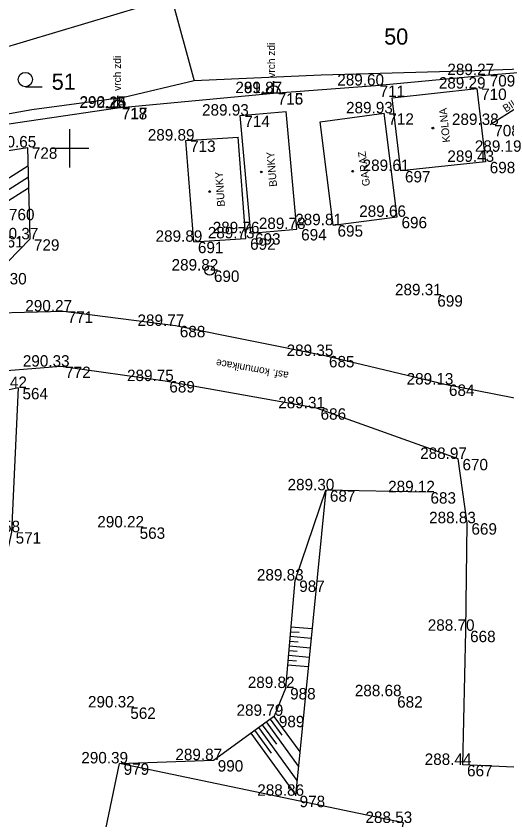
# Model space of a CAD drawing. Extents: x -599970 to -599524, y -1154772 to -1154457.
# Drawn here: x -599702.82 to -599677.05, y -1154635.29 to -1154593.05 of the extents above; entities that cross this region are included whole.
import ezdxf

# ---------------------------------------------------------------- set-up
doc = ezdxf.new("R2010")
doc.units = 0
for name, color, linetype in [('Z-BUDOVY', 7, 'Continuous'), ('Z-KANALIZACNI SACHTY VPUSTI', 7, 'Continuous'), ('Z-KATASTRALNI MAPA', 7, 'Continuous'), ('Z-KRIZKY CTVERCOVE SITE', 7, 'Continuous'), ('Z-PLOT BETONOVY', 7, 'Continuous'), ('Z-PLOT DRATENY', 7, 'Continuous'), ('Z-PODROBNE BODY', 7, 'Continuous'), ('Z-PODROBNE BODY-CISLO', 7, 'Continuous'), ('Z-PODROBNE BODY-VYSKA', 7, 'Continuous'), ('Z-POPISY OBJEKTU A ZPEVNENYCH PLOCH', 7, 'Continuous'), ('Z-SCHODY', 7, 'Continuous'), ('Z-SRAFOVANI SVAHU', 7, 'Continuous'), ('Z-TERENNI HRANY PATY', 7, 'Continuous'), ('Z-VYSKOVE BODY', 7, 'Continuous'), ('Z-ZPEVNENE PLOCHY', 7, 'Continuous')]:
    doc.layers.add(name, color=color, linetype=linetype)

msp = doc.modelspace()

# ---------------------------------------------------------------- linework, layer by layer
at = {"layer": 'Z-BUDOVY'}
for p, q in [((-599688.08, -1154604.24), (-599688.64, -1154598.06)), ((-599682.81, -1154603.6), (-599683.5, -1154598.16)), ((-599690.76, -1154604.73), (-599691.17, -1154599.41))]:
    msp.add_line(p, q, dxfattribs=at)
for points in [[(-599682.63, -1154601.19), (-599683.08, -1154597.34), (-599678.63, -1154596.86), (-599678.18, -1154600.71), (-599682.63, -1154601.19)], [(-599690.5, -1154604.46), (-599691.06, -1154598.28), (-599688.64, -1154598.06)], [(-599686.17, -1154604.04), (-599686.86, -1154598.6), (-599683.5, -1154598.16)], [(-599693.5, -1154604.91), (-599693.91, -1154599.59), (-599691.17, -1154599.41)], [(-599686.17, -1154604.04), (-599682.81, -1154603.6)], [(-599690.5, -1154604.46), (-599688.08, -1154604.24)], [(-599693.5, -1154604.91), (-599690.76, -1154604.73)], [(-599684.7, -1154645.47), (-599699.48, -1154642.29), (-599697.4, -1154632.32)], [(-599684.7, -1154645.47), (-599682.48, -1154635.45), (-599697.4, -1154632.32)]]:
    msp.add_lwpolyline(points, dxfattribs=at)
at = {"layer": 'Z-KANALIZACNI SACHTY VPUSTI'}
msp.add_circle((-599692.66, -1154606.42), 0.25, dxfattribs=at)
at = {"layer": 'Z-KATASTRALNI MAPA'}
for p, q in [((-599694.67, -1154592.08), (-599720.86, -1154599.93)), ((-599694.67, -1154592.08), (-599693.47, -1154596.46)), ((-599702.336, -1154596.76), (-599701.461, -1154596.76))]:
    msp.add_line(p, q, dxfattribs=at)
for points in [[(-599673.37, -1154595.74), (-599678.74, -1154595.92), (-599686.81, -1154596.16), (-599693.47, -1154596.46)], [(-599693.47, -1154596.46), (-599697.17, -1154597.32), (-599702, -1154597.98), (-599710.88, -1154599.57), (-599714.17, -1154599.94), (-599720.86, -1154599.93)]]:
    msp.add_lwpolyline(points, dxfattribs=at)
msp.add_circle((-599702.336, -1154596.385), 0.375, dxfattribs=at)
at = {"layer": 'Z-KRIZKY CTVERCOVE SITE'}
for p, q in [((-599700, -1154601), (-599700, -1154599)), ((-599699, -1154600), (-599701, -1154600))]:
    msp.add_line(p, q, dxfattribs=at)
at = {"layer": 'Z-PLOT BETONOVY'}
msp.add_lwpolyline([(-599697.5, -1154597.88), (-599689.31, -1154597.1), (-599683.96, -1154596.7), (-599678.18, -1154596.15), (-599673.7, -1154595.78)], dxfattribs=at)
at = {"layer": 'Z-PLOT DRATENY'}
for points in [[(-599741.2, -1154597.57), (-599735.3, -1154599.31), (-599728.67, -1154601.06), (-599725.81, -1154601.09), (-599719.24, -1154600.72), (-599713.57, -1154600.28), (-599704.41, -1154598.89), (-599697.5, -1154597.88)], [(-599681.29, -1154618.07), (-599686.57, -1154617.97), (-599688.16, -1154634.02)]]:
    msp.add_lwpolyline(points, dxfattribs=at)
at = {"layer": 'Z-PODROBNE BODY'}
for p, q in [((-599678.18, -1154596.15), (-599678.18, -1154596.15)), ((-599689.31, -1154597.1), (-599689.31, -1154597.1)), ((-599689.31, -1154597.1), (-599689.31, -1154597.1)), ((-599683.96, -1154596.7), (-599683.96, -1154596.7)), ((-599678.63, -1154596.86), (-599678.63, -1154596.86)), ((-599697.5, -1154597.88), (-599697.5, -1154597.88)), ((-599697.49, -1154597.86), (-599697.49, -1154597.86)), ((-599691.06, -1154598.28), (-599691.06, -1154598.28)), ((-599683.5, -1154598.16), (-599683.5, -1154598.16)), ((-599677.94, -1154598.77), (-599677.94, -1154598.77)), ((-599693.91, -1154599.59), (-599693.91, -1154599.59)), ((-599702.22, -1154599.95), (-599702.22, -1154599.95)), ((-599678.18, -1154600.71), (-599678.18, -1154600.71)), ((-599682.63, -1154601.19), (-599682.63, -1154601.19)), ((-599682.81, -1154603.6), (-599682.81, -1154603.6)), ((-599688.08, -1154604.24), (-599688.08, -1154604.24)), ((-599686.17, -1154604.04), (-599686.17, -1154604.04)), ((-599690.5, -1154604.46), (-599690.5, -1154604.46)), ((-599702.11, -1154604.78), (-599702.11, -1154604.78)), ((-599693.5, -1154604.91), (-599693.5, -1154604.91)), ((-599690.76, -1154604.73), (-599690.76, -1154604.73)), ((-599692.66, -1154606.42), (-599692.66, -1154606.42)), ((-599680.93, -1154607.72), (-599680.93, -1154607.72)), ((-599700.34, -1154608.57), (-599700.34, -1154608.57)), ((-599694.45, -1154609.33), (-599694.45, -1154609.33)), ((-599686.62, -1154610.91), (-599686.62, -1154610.91)), ((-599700.47, -1154611.47), (-599700.47, -1154611.47)), ((-599695, -1154612.23), (-599695, -1154612.23)), ((-599702.71, -1154612.59), (-599702.71, -1154612.59)), ((-599680.32, -1154612.41), (-599680.32, -1154612.41)), ((-599687.06, -1154613.66), (-599687.06, -1154613.66)), ((-599679.61, -1154616.32), (-599679.61, -1154616.32)), ((-599686.57, -1154617.97), (-599686.57, -1154617.97)), ((-599681.29, -1154618.07), (-599681.29, -1154618.07)), ((-599696.56, -1154619.92), (-599696.56, -1154619.92)), ((-599679.14, -1154619.7), (-599679.14, -1154619.7)), ((-599688.18, -1154622.71), (-599688.18, -1154622.71)), ((-599679.21, -1154625.35), (-599679.21, -1154625.35)), ((-599688.66, -1154628.36), (-599688.66, -1154628.36)), ((-599683.04, -1154628.79), (-599683.04, -1154628.79)), ((-599697.05, -1154629.38), (-599697.05, -1154629.38)), ((-599689.25, -1154629.82), (-599689.25, -1154629.82)), ((-599692.46, -1154632.15), (-599692.46, -1154632.15)), ((-599697.4, -1154632.32), (-599697.4, -1154632.32)), ((-599679.37, -1154632.4), (-599679.37, -1154632.4)), ((-599688.16, -1154634.02), (-599688.16, -1154634.02))]:
    msp.add_line(p, q, dxfattribs=at)
at = {"layer": 'Z-SCHODY'}
for centre in [(-599680.94, -1154598.94), (-599689.95, -1154601.24), (-599685.15, -1154601.2), (-599692.66, -1154602.27)]:
    msp.add_circle(centre, 0.0438, dxfattribs=at)
at = {"layer": 'Z-SRAFOVANI SVAHU'}
for points in [[(-599704.09, -1154602.11), (-599702.2, -1154600.92)], [(-599703.83, -1154602.54), (-599702.18, -1154601.5)], [(-599703.56, -1154602.96), (-599702.17, -1154602.08)], [(-599688.41, -1154625.4), (-599687.97, -1154625.43)], [(-599688.39, -1154625.15), (-599687.29, -1154625.24)], [(-599688.43, -1154625.64), (-599687.34, -1154625.74)], [(-599688.47, -1154626.14), (-599687.39, -1154626.24)], [(-599688.45, -1154625.89), (-599688.02, -1154625.93)], [(-599688.51, -1154626.64), (-599687.44, -1154626.73)], [(-599688.49, -1154626.39), (-599688.06, -1154626.43)], [(-599688.54, -1154626.89), (-599688.11, -1154626.93)], [(-599688.56, -1154627.14), (-599687.49, -1154627.23)], [(-599689.49, -1154630), (-599688.88, -1154630.84)], [(-599689.29, -1154629.85), (-599687.93, -1154631.72)], [(-599690.1, -1154630.44), (-599688.08, -1154633.22)], [(-599689.9, -1154630.29), (-599689.16, -1154631.31)], [(-599689.69, -1154630.14), (-599688.01, -1154632.47)], [(-599690.5, -1154630.73), (-599688.15, -1154633.97)], [(-599690.3, -1154630.58), (-599689.43, -1154631.79)]]:
    msp.add_lwpolyline(points, dxfattribs=at)
at = {"layer": 'Z-TERENNI HRANY PATY'}
for points in [[(-599729.05, -1154602.01), (-599721.76, -1154601.98), (-599713.7, -1154601.68), (-599707.23, -1154600.75), (-599702.22, -1154599.95), (-599702.11, -1154604.78), (-599703.83, -1154606.55), (-599707.44, -1154607.94), (-599715.66, -1154610.06), (-599723.72, -1154611.89), (-599730.02, -1154613.49), (-599734.59, -1154613.85), (-599735.4, -1154613.47), (-599737.38, -1154610.51), (-599738.93, -1154607.87), (-599737.97, -1154605.84), (-599735.06, -1154604.09), (-599729.05, -1154602.01)], [(-599702.71, -1154612.59), (-599705.57, -1154613.21), (-599706.65, -1154620.67), (-599709.89, -1154628.2), (-599711.28, -1154633.06)], [(-599702.71, -1154612.59), (-599703.07, -1154620.17), (-599705.22, -1154630.05), (-599705.67, -1154634.21), (-599706.5, -1154641.82), (-599707.05, -1154645.89), (-599706.85, -1154650.78)], [(-599697.4, -1154632.32), (-599692.46, -1154632.15), (-599689.25, -1154629.82), (-599688.66, -1154628.36), (-599688.18, -1154622.71), (-599686.57, -1154617.97)]]:
    msp.add_lwpolyline(points, dxfattribs=at)
at = {"layer": 'Z-VYSKOVE BODY'}
for p, q in [((-599689.31, -1154596.475), (-599689.31, -1154596.725)), ((-599689.31, -1154596.725), (-599689.31, -1154596.475)), ((-599689.31, -1154597.1), (-599689.31, -1154596.475)), ((-599689.31, -1154596.475), (-599689.31, -1154596.725)), ((-599688.685, -1154597.1), (-599689.935, -1154597.1)), ((-599689.935, -1154597.1), (-599689.31, -1154597.1)), ((-599688.685, -1154597.1), (-599689.31, -1154597.1)), ((-599697.49, -1154597.235), (-599697.49, -1154597.485)), ((-599697.49, -1154597.485), (-599697.49, -1154597.235)), ((-599697.49, -1154597.86), (-599697.49, -1154597.235)), ((-599697.49, -1154597.235), (-599697.49, -1154597.485)), ((-599696.865, -1154597.86), (-599698.115, -1154597.86)), ((-599698.115, -1154597.86), (-599697.49, -1154597.86)), ((-599696.865, -1154597.86), (-599697.49, -1154597.86))]:
    msp.add_line(p, q, dxfattribs=at)
for centre, start, end in [((-599689.31, -1154597.1), 90, 180), ((-599689.31, -1154597.1), 0, 90), ((-599697.49, -1154597.86), 90, 180), ((-599697.49, -1154597.86), 0, 90)]:
    msp.add_arc(centre, 0.375, start, end, dxfattribs=at)
at = {"layer": 'Z-ZPEVNENE PLOCHY'}
for points in [[(-599673.47, -1154595.92), (-599677.94, -1154598.77)], [(-599671.02, -1154617.03), (-599671.63, -1154613.35), (-599675.05, -1154613.45), (-599680.32, -1154612.41), (-599686.62, -1154610.91), (-599694.45, -1154609.33), (-599700.34, -1154608.57), (-599705.79, -1154608.71), (-599715.78, -1154610.69), (-599725.58, -1154612.61), (-599730.02, -1154613.49), (-599735.64, -1154614.56), (-599743.95, -1154616.26), (-599754.96, -1154619.25), (-599762.63, -1154622.27), (-599761.65, -1154625.43)], [(-599671.02, -1154617.03), (-599674, -1154617.11), (-599674.74, -1154618.09), (-599672.97, -1154619.61), (-599672.99, -1154619.63), (-599673.43, -1154624.97), (-599672.1, -1154632.73), (-599679.37, -1154632.4), (-599679.21, -1154625.35), (-599679.14, -1154619.7), (-599679.61, -1154616.32), (-599687.06, -1154613.66), (-599695, -1154612.23), (-599700.47, -1154611.47), (-599705.51, -1154611.86), (-599715.16, -1154613.61), (-599724.96, -1154615.5), (-599735.23, -1154617.18), (-599743.14, -1154619.2), (-599754.14, -1154621.91)]]:
    msp.add_lwpolyline(points, dxfattribs=at)

# ---------------------------------------------------------------- texts
at = {"layer": 'Z-KATASTRALNI MAPA'}
for s, p in [('50', (-599683.499, -1154594.55)), ('51', (-599700.952, -1154596.92))]:
    msp.add_text(s, height=0.85, dxfattribs=at).set_placement(p)
at = {"layer": 'Z-PODROBNE BODY-CISLO'}
for s, p in [(' 709', (-599678.18, -1154596.75)), (' 716', (-599689.31, -1154597.7)), (' 715', (-599689.31, -1154597.7)), (' 711', (-599683.96, -1154597.3)), (' 710', (-599678.63, -1154597.46)), (' 718', (-599697.5, -1154598.48)), (' 717', (-599697.49, -1154598.46)), (' 714', (-599691.06, -1154598.88)), (' 712', (-599683.5, -1154598.76)), (' 708', (-599677.94, -1154599.37)), (' 713', (-599693.91, -1154600.19)), (' 728', (-599702.22, -1154600.55)), (' 698', (-599678.18, -1154601.31)), (' 697', (-599682.63, -1154601.79)), (' 760', (-599703.42, -1154603.78)), (' 696', (-599682.81, -1154604.2)), (' 694', (-599688.08, -1154604.84)), (' 695', (-599686.17, -1154604.64)), (' 761', (-599703.99, -1154605.21)), (' 692', (-599690.76, -1154605.33)), (' 693', (-599690.5, -1154605.06)), (' 729', (-599702.11, -1154605.38)), (' 691', (-599693.5, -1154605.51)), (' 690', (-599692.66, -1154607.02)), (' 730', (-599703.83, -1154607.15)), (' 699', (-599680.93, -1154608.32)), (' 771', (-599700.34, -1154609.17)), (' 688', (-599694.45, -1154609.93)), (' 685', (-599686.62, -1154611.51)), (' 772', (-599700.47, -1154612.07)), (' 689', (-599695, -1154612.83)), (' 564', (-599702.71, -1154613.19)), (' 684', (-599680.32, -1154613.01)), (' 686', (-599687.06, -1154614.26)), (' 670', (-599679.61, -1154616.92)), (' 687', (-599686.57, -1154618.57)), (' 683', (-599681.29, -1154618.67)), (' 563', (-599696.56, -1154620.52)), (' 669', (-599679.14, -1154620.3)), (' 571', (-599703.07, -1154620.77)), (' 987', (-599688.18, -1154623.31)), (' 668', (-599679.21, -1154625.95)), (' 988', (-599688.66, -1154628.96)), (' 682', (-599683.04, -1154629.39)), (' 562', (-599697.05, -1154629.98)), (' 989', (-599689.25, -1154630.42)), (' 990', (-599692.46, -1154632.75)), (' 979', (-599697.4, -1154632.92)), (' 667', (-599679.37, -1154633)), (' 978', (-599688.16, -1154634.62))]:
    msp.add_text(s, height=0.6, dxfattribs=at).set_placement(p)
at = {"layer": 'Z-PODROBNE BODY-VYSKA'}
for s, p in [('289.27 ', (-599680.18, -1154596.15)), ('289.60 ', (-599685.96, -1154596.7)), ('289.29 ', (-599680.63, -1154596.86)), ('289.87 ', (-599691.31, -1154597.1)), ('291.87 ', (-599691.31, -1154597.1)), ('290.24 ', (-599699.5, -1154597.88)), ('292.15 ', (-599699.49, -1154597.86)), ('289.93 ', (-599693.06, -1154598.28)), ('289.93 ', (-599685.5, -1154598.16)), ('289.38 ', (-599679.94, -1154598.77)), ('289.89 ', (-599695.91, -1154599.59)), ('290.65 ', (-599704.22, -1154599.95)), ('289.19 ', (-599678.74, -1154600.18)), ('289.43 ', (-599680.18, -1154600.71)), ('289.61 ', (-599684.63, -1154601.19)), ('289.66 ', (-599684.81, -1154603.6)), ('289.81 ', (-599688.17, -1154604.04)), ('289.76 ', (-599692.5, -1154604.46)), ('289.78 ', (-599690.08, -1154604.24)), ('290.37 ', (-599704.11, -1154604.78)), ('289.89 ', (-599695.5, -1154604.91)), ('289.73 ', (-599692.76, -1154604.73)), ('289.82 ', (-599694.66, -1154606.42)), ('289.31 ', (-599682.93, -1154607.72)), ('290.27 ', (-599702.34, -1154608.57)), ('289.77 ', (-599696.45, -1154609.33)), ('289.35 ', (-599688.62, -1154610.91)), ('290.33 ', (-599702.47, -1154611.47)), ('289.75 ', (-599697, -1154612.23)), ('289.13 ', (-599682.32, -1154612.41)), ('290.42 ', (-599704.71, -1154612.59)), ('289.31 ', (-599689.06, -1154613.66)), ('288.97 ', (-599681.61, -1154616.32)), ('289.30 ', (-599688.57, -1154617.97)), ('289.12 ', (-599683.29, -1154618.07)), ('290.22 ', (-599698.56, -1154619.92)), ('288.83 ', (-599681.14, -1154619.7)), ('290.58 ', (-599705.07, -1154620.17)), ('289.83 ', (-599690.18, -1154622.71)), ('288.70 ', (-599681.21, -1154625.35)), ('289.82 ', (-599690.66, -1154628.36)), ('288.68 ', (-599685.04, -1154628.79)), ('290.32 ', (-599699.05, -1154629.38)), ('289.79 ', (-599691.25, -1154629.82)), ('290.39 ', (-599699.4, -1154632.32)), ('289.87 ', (-599694.46, -1154632.15)), ('288.44 ', (-599681.37, -1154632.4)), ('288.86 ', (-599690.16, -1154634.02)), ('288.53 ', (-599684.48, -1154635.45))]:
    msp.add_text(s, height=0.6, dxfattribs=at).set_placement(p)
at = {"layer": 'Z-POPISY OBJEKTU A ZPEVNENYCH PLOCH'}
for s, rotation, p in [('BILLBOARD', 32.5209, (-599677.11, -1154598.12)), ('KOLNA', 96.1564, (-599680.03, -1154599.67)), ('BUNKY', 95.1944, (-599689.12, -1154602)), ('GARAZ', 97.4606, (-599684.24, -1154601.96)), ('BUNKY', 93.7586, (-599691.86, -1154603.05)), ('asf. komunikace', 169.7904, (-599688.49, -1154611.76))]:
    msp.add_text(s, height=0.4, rotation=rotation, dxfattribs=at).set_placement(p)
at = {"layer": 'Z-VYSKOVE BODY'}
for p in [(-599689.23, -1154596.29), (-599697.32, -1154596.98)]:
    msp.add_text('vrch zdi', height=0.4, rotation=90, dxfattribs=at).set_placement(p)

doc.saveas('drawing.dxf')
